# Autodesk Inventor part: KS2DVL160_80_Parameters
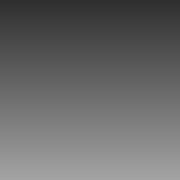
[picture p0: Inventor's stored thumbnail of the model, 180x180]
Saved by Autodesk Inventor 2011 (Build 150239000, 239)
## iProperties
Created: 2010-11
Document SubType Name: Modeling
Designer: TB
Density: 1 g/cm^3
Slaglengde: 100,000 mm
Vinkel_Minusport: 0.00 deg
Forlengelse_rør: 0.000 mm
Minusport2: 180.00 deg
Author: TB
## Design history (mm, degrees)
other parameters: "Slaglengde" = 100 [user parameter], "Forlengelse_rør" = 0 [user parameter], "Vinkel_Minusport" = 0 deg [user parameter], "Minusport2" = 180 deg [user parameter]
